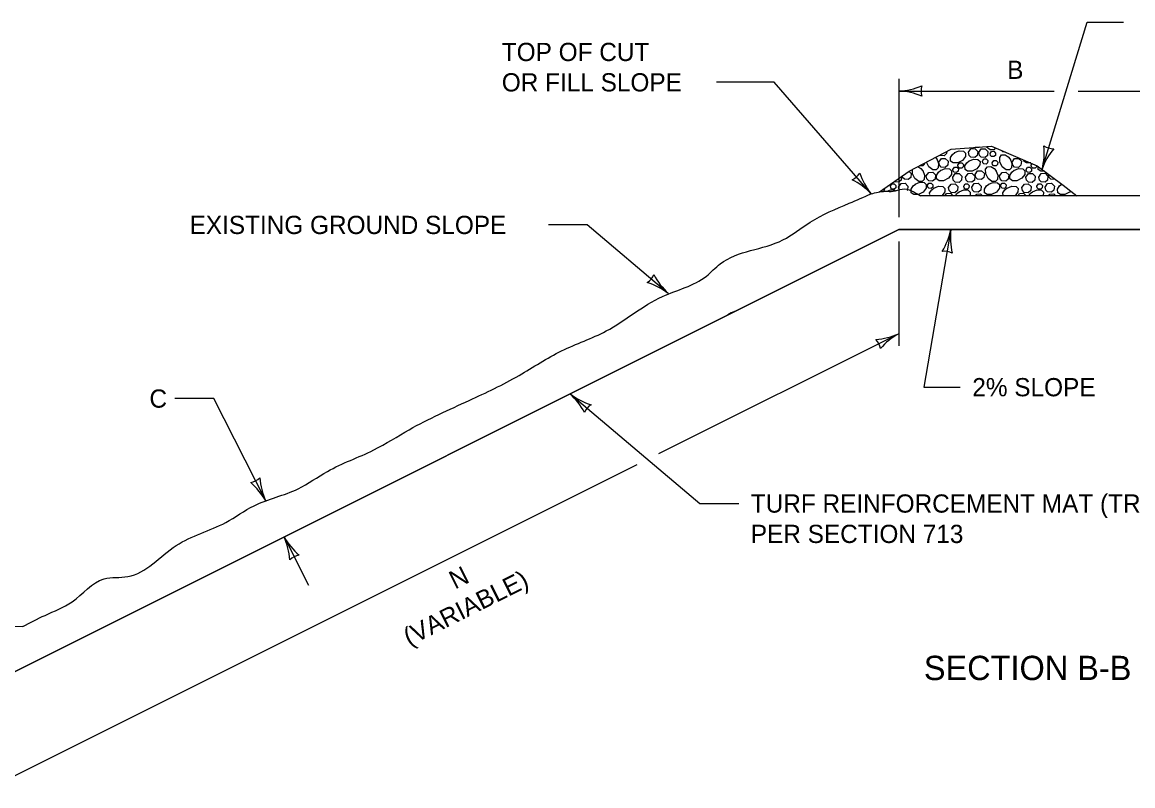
# Model space of a CAD drawing. Extents: x 49991.4 to 50021, y 49987.6 to 50011.4.
# Drawn here: x 50010.982 to 50014.64, y 49990.831 to 49993.345 of the extents above; entities that cross this region are included whole.
import ezdxf

# ---------------------------------------------------------------- set-up
doc = ezdxf.new("R2010")
doc.units = 0
for name, color, linetype in [('Level 1', 7, 'Continuous'), ('Level 2', 7, 'Continuous'), ('Level 3', 7, 'Continuous')]:
    doc.layers.add(name, color=color, linetype=linetype)

msp = doc.modelspace()

# ---------------------------------------------------------------- linework, layer by layer
at = {"layer": 'Level 1'}
for p, q in [((50014.842, 49992.7741), (50013.9411, 49992.7741)), ((50013.8692, 49992.663), (50014.7514, 49992.663))]:
    msp.add_line(p, q, dxfattribs=at)
for points in [[(50013.8062, 49992.7866), (50013.904, 49992.8548), (50014.0418, 49992.9278), (50014.1745, 49992.937), (50014.3255, 49992.8729), (50014.4104, 49992.8085), (50014.4557, 49992.7741)], [(50014.0275, 49992.9203), (50014.0268, 49992.9126), (50014.0187, 49992.9059), (50014.0058, 49992.9068), (50014.0045, 49992.9081)], [(50014.0532, 49992.916), (50014.0686, 49992.9221), (50014.0826, 49992.9208), (50014.0893, 49992.9145), (50014.0891, 49992.903), (50014.079, 49992.8901), (50014.0633, 49992.8822), (50014.0485, 49992.8819), (50014.0401, 49992.8879), (50014.0393, 49992.8997), (50014.0461, 49992.9102), (50014.0538, 49992.9164)], [(50014.0989, 49992.917), (50014.1071, 49992.9287), (50014.1202, 49992.9295), (50014.1293, 49992.92), (50014.128, 49992.9068), (50014.1199, 49992.9001), (50014.107, 49992.901), (50014.1009, 49992.9069), (50014.099, 49992.917)], [(50014.1349, 49992.9343), (50014.1332, 49992.9325), (50014.1218, 49992.9327), (50014.121, 49992.9333)], [(50014.1327, 49992.9165), (50014.1409, 49992.9282), (50014.1539, 49992.929), (50014.163, 49992.9195), (50014.1617, 49992.9063), (50014.1536, 49992.8996), (50014.1407, 49992.9005), (50014.1346, 49992.9064), (50014.1327, 49992.9165)], [(50014.1878, 49992.9314), (50014.1818, 49992.9251), (50014.1704, 49992.9253), (50014.1574, 49992.9355), (50014.1572, 49992.9358)], [(50014.17, 49992.913), (50014.1749, 49992.9199), (50014.1827, 49992.9204), (50014.1882, 49992.9147), (50014.1874, 49992.9068), (50014.1825, 49992.9028), (50014.1748, 49992.9033), (50014.1711, 49992.9069), (50014.17, 49992.9129)], [(50014.2198, 49992.9178), (50014.2124, 49992.9184), (50014.2076, 49992.923)], [(50015.5568, 49992.9155), (50015.0142, 49992.7795), (50014.842, 49992.7186), (50014.7514, 49992.663), (50013.8692, 49992.663), (50010.8919, 49991.1744), (50010.2132, 49991.2052)], [(50013.9535, 49992.8811), (50013.9531, 49992.8764), (50013.9482, 49992.8724), (50013.9405, 49992.873), (50013.9397, 49992.8737)], [(50013.9944, 49992.8953), (50014.0005, 49992.8799), (50013.9993, 49992.8658), (50013.9929, 49992.8591), (50013.9815, 49992.8594), (50013.9685, 49992.8695), (50013.9608, 49992.8849)], [(50013.9901, 49992.9005), (50013.9948, 49992.8946)], [(50014.0014, 49992.8845), (50014.0096, 49992.8961), (50014.0226, 49992.8969), (50014.0317, 49992.8874), (50014.0304, 49992.8742), (50014.0223, 49992.8675), (50014.0094, 49992.8684), (50014.0033, 49992.8743), (50014.0014, 49992.8845)], [(50014.0643, 49992.8749), (50014.0692, 49992.8819), (50014.077, 49992.8823), (50014.0825, 49992.8767), (50014.0817, 49992.8688), (50014.0768, 49992.8647), (50014.0691, 49992.8653), (50014.0654, 49992.8688), (50014.0643, 49992.8749)], [(50014.1008, 49992.8886), (50014.1161, 49992.8947), (50014.1302, 49992.8935), (50014.1369, 49992.8871), (50014.1367, 49992.8757), (50014.1265, 49992.8627), (50014.1108, 49992.8548), (50014.096, 49992.8546), (50014.0877, 49992.8605), (50014.0869, 49992.8723), (50014.0937, 49992.8828), (50014.1014, 49992.889)], [(50014.1446, 49992.8883), (50014.1495, 49992.8953), (50014.1574, 49992.8958), (50014.1628, 49992.8901), (50014.162, 49992.8822), (50014.1572, 49992.8782), (50014.1494, 49992.8787), (50014.1458, 49992.8823), (50014.1446, 49992.8883)], [(50014.1769, 49992.8826), (50014.1818, 49992.8896), (50014.1896, 49992.89), (50014.1951, 49992.8844), (50014.1943, 49992.8764), (50014.1895, 49992.8724), (50014.1817, 49992.873), (50014.1781, 49992.8765), (50014.1769, 49992.8826)], [(50014.2356, 49992.8953), (50014.2417, 49992.8799), (50014.2405, 49992.8658), (50014.2341, 49992.8591), (50014.2227, 49992.8594), (50014.2097, 49992.8695), (50014.2019, 49992.8852), (50014.2016, 49992.9), (50014.2075, 49992.9083), (50014.2193, 49992.9091), (50014.2299, 49992.9024), (50014.236, 49992.8946)], [(50014.2426, 49992.8845), (50014.2508, 49992.8961), (50014.2639, 49992.8969), (50014.273, 49992.8874), (50014.2717, 49992.8742), (50014.2636, 49992.8675), (50014.2507, 49992.8684), (50014.2446, 49992.8743), (50014.2426, 49992.8845)], [(50014.3037, 49992.8822), (50014.2897, 49992.8819), (50014.2814, 49992.8879), (50014.2811, 49992.8918)], [(50013.9031, 49992.8542), (50013.91, 49992.8471), (50013.9087, 49992.8338), (50013.9006, 49992.8271), (50013.8877, 49992.8281), (50013.8816, 49992.834), (50013.8807, 49992.8386)], [(50013.948, 49992.8566), (50013.9541, 49992.8412), (50013.9529, 49992.8272), (50013.9465, 49992.8205), (50013.9351, 49992.8207), (50013.9221, 49992.8308), (50013.9142, 49992.8465), (50013.914, 49992.8601)], [(50013.9325, 49992.8699), (50013.9422, 49992.8637), (50013.9484, 49992.856)], [(50013.9598, 49992.8394), (50013.968, 49992.851), (50013.9811, 49992.8518), (50013.9902, 49992.8424), (50013.9889, 49992.8291), (50013.9808, 49992.8224), (50013.9679, 49992.8233), (50013.9618, 49992.8292), (50013.9598, 49992.8394)], [(50014.0071, 49992.8574), (50014.0224, 49992.8634), (50014.0365, 49992.8622), (50014.0432, 49992.8559), (50014.043, 49992.8444), (50014.0328, 49992.8314), (50014.0171, 49992.8236), (50014.0023, 49992.8233), (50013.994, 49992.8292), (50013.9932, 49992.841), (50014, 49992.8516), (50014.0077, 49992.8577)], [(50014.0468, 49992.8351), (50014.055, 49992.8467), (50014.0681, 49992.8475), (50014.0772, 49992.838), (50014.0759, 49992.8248), (50014.0678, 49992.8181), (50014.0549, 49992.819), (50014.0488, 49992.8249), (50014.0468, 49992.8351)], [(50014.0473, 49992.8607), (50014.0523, 49992.8677), (50014.0601, 49992.8681), (50014.0656, 49992.8625), (50014.0648, 49992.8545), (50014.0599, 49992.8505), (50014.0522, 49992.8511), (50014.0485, 49992.8546), (50014.0474, 49992.8607)], [(50014.0891, 49992.8355), (50014.0973, 49992.8472), (50014.1104, 49992.8479), (50014.1195, 49992.8385), (50014.1182, 49992.8253), (50014.1101, 49992.8186), (50014.0971, 49992.8195), (50014.0911, 49992.8254), (50014.0891, 49992.8355)], [(50014.1209, 49992.8441), (50014.1291, 49992.8557), (50014.1422, 49992.8565), (50014.1513, 49992.8471), (50014.1499, 49992.8338), (50014.1419, 49992.8271), (50014.1289, 49992.8281), (50014.1229, 49992.834), (50014.1209, 49992.8441)], [(50014.1893, 49992.8566), (50014.1953, 49992.8412), (50014.1941, 49992.8272), (50014.1878, 49992.8205), (50014.1763, 49992.8207), (50014.1633, 49992.8308), (50014.1555, 49992.8465), (50014.1552, 49992.8613), (50014.1611, 49992.8697), (50014.1729, 49992.8705), (50014.1835, 49992.8637), (50014.1897, 49992.856)], [(50014.2011, 49992.8394), (50014.2093, 49992.851), (50014.2224, 49992.8518), (50014.2314, 49992.8424), (50014.2301, 49992.8291), (50014.222, 49992.8224), (50014.2091, 49992.8233), (50014.203, 49992.8292), (50014.2011, 49992.8394)], [(50014.2483, 49992.8574), (50014.2637, 49992.8634), (50014.2778, 49992.8622), (50014.2844, 49992.8559), (50014.2842, 49992.8444), (50014.2741, 49992.8314), (50014.2584, 49992.8236), (50014.2436, 49992.8233), (50014.2352, 49992.8292), (50014.2345, 49992.841), (50014.2412, 49992.8516), (50014.249, 49992.8577)], [(50014.288, 49992.8351), (50014.2962, 49992.8467), (50014.3093, 49992.8475), (50014.3184, 49992.838), (50014.3171, 49992.8248), (50014.309, 49992.8181), (50014.2961, 49992.819), (50014.29, 49992.8249), (50014.2881, 49992.8351)], [(50014.2886, 49992.8607), (50014.2935, 49992.8677), (50014.3014, 49992.8681), (50014.3068, 49992.8625), (50014.306, 49992.8545), (50014.3012, 49992.8505), (50014.2934, 49992.8511), (50014.2898, 49992.8546), (50014.2886, 49992.8607)], [(50014.3055, 49992.8749), (50014.309, 49992.8799)], [(50014.3234, 49992.8738), (50014.3229, 49992.8688), (50014.3181, 49992.8647), (50014.3103, 49992.8653), (50014.3067, 49992.8688), (50014.3055, 49992.8749)], [(50014.3494, 49992.8548), (50014.3373, 49992.8546), (50014.3289, 49992.8605), (50014.3283, 49992.8709)], [(50014.3303, 49992.8355), (50014.3385, 49992.8472), (50014.3516, 49992.8479), (50014.3607, 49992.8385), (50014.3594, 49992.8253), (50014.3513, 49992.8186), (50014.3384, 49992.8195), (50014.3323, 49992.8254), (50014.3303, 49992.8355)], [(50014.3844, 49992.8282), (50014.3831, 49992.8271), (50014.3702, 49992.8281), (50014.3641, 49992.834), (50014.3621, 49992.8441)], [(50013.8418, 49992.8057), (50013.8468, 49992.8127), (50013.8546, 49992.8132), (50013.8601, 49992.8075), (50013.8593, 49992.7996), (50013.8544, 49992.7955), (50013.8467, 49992.7961), (50013.843, 49992.7996), (50013.8419, 49992.8057)], [(50013.878, 49992.8367), (50013.8769, 49992.8253), (50013.8688, 49992.8186), (50013.8559, 49992.8195), (50013.8549, 49992.8205)], [(50013.8687, 49992.8027), (50013.8769, 49992.8143), (50013.89, 49992.8151), (50013.8991, 49992.8057), (50013.8978, 49992.7924), (50013.8969, 49992.7917)], [(50013.9237, 49992.8122), (50013.9391, 49992.8183), (50013.9532, 49992.8171), (50013.9598, 49992.8107), (50013.9596, 49992.7993), (50013.9495, 49992.7863), (50013.9338, 49992.7784), (50013.919, 49992.7782), (50013.9106, 49992.7841), (50013.9099, 49992.7959), (50013.9166, 49992.8064), (50013.9244, 49992.8126)], [(50013.9636, 49992.8084), (50013.9685, 49992.8154), (50013.9763, 49992.8158), (50013.9818, 49992.8102), (50013.981, 49992.8023), (50013.9761, 49992.7982), (50013.9684, 49992.7988), (50013.9647, 49992.8023), (50013.9636, 49992.8084)], [(50014.0334, 49992.8009), (50014.0416, 49992.8126), (50014.0546, 49992.8133), (50014.0637, 49992.8039), (50014.0624, 49992.7907), (50014.0543, 49992.7839), (50014.0414, 49992.7849), (50014.0353, 49992.7908), (50014.0334, 49992.8009)], [(50014.0831, 49992.8057), (50014.088, 49992.8127), (50014.0959, 49992.8132), (50014.1013, 49992.8075), (50014.1005, 49992.7996), (50014.0957, 49992.7955), (50014.0879, 49992.7961), (50014.0843, 49992.7996), (50014.0831, 49992.8057)], [(50014.11, 49992.8027), (50014.1181, 49992.8143), (50014.1312, 49992.8151), (50014.1403, 49992.8057), (50014.139, 49992.7924), (50014.1309, 49992.7857), (50014.118, 49992.7867), (50014.1119, 49992.7926), (50014.11, 49992.8027)], [(50014.165, 49992.812), (50014.1803, 49992.8181), (50014.1944, 49992.8169), (50014.2011, 49992.8105), (50014.2009, 49992.7991), (50014.1907, 49992.7861), (50014.175, 49992.7782), (50014.1602, 49992.778), (50014.1519, 49992.7839), (50014.1511, 49992.7957), (50014.1578, 49992.8062), (50014.1656, 49992.8124)], [(50014.2048, 49992.8084), (50014.2097, 49992.8154), (50014.2176, 49992.8158), (50014.223, 49992.8102), (50014.2222, 49992.8023), (50014.2174, 49992.7982), (50014.2096, 49992.7988), (50014.206, 49992.8023), (50014.2048, 49992.8084)], [(50014.2746, 49992.8009), (50014.2828, 49992.8126), (50014.2959, 49992.8133), (50014.305, 49992.8039), (50014.3037, 49992.7907), (50014.2956, 49992.7839), (50014.2827, 49992.7849), (50014.2766, 49992.7908), (50014.2746, 49992.8009)], [(50014.3243, 49992.8057), (50014.3293, 49992.8127), (50014.3371, 49992.8132), (50014.3426, 49992.8075), (50014.3418, 49992.7996), (50014.3369, 49992.7955), (50014.3292, 49992.7961), (50014.3255, 49992.7996), (50014.3243, 49992.8057)], [(50014.3512, 49992.8027), (50014.3594, 49992.8143), (50014.3725, 49992.8151), (50014.3816, 49992.8057), (50014.3803, 49992.7924), (50014.3722, 49992.7857), (50014.3593, 49992.7867), (50014.3532, 49992.7926), (50014.3512, 49992.8027)], [(50014.4349, 49992.7899), (50014.4319, 49992.7861), (50014.4162, 49992.7782), (50014.4014, 49992.778), (50014.3931, 49992.7839), (50014.3923, 49992.7957), (50014.3991, 49992.8062), (50014.406, 49992.8118)], [(50013.8219, 49992.7975), (50013.8212, 49992.7907), (50013.818, 49992.788)], [(50013.8313, 49992.7888), (50013.8422, 49992.7931), (50013.8563, 49992.7919), (50013.8581, 49992.7902)], [(50013.8704, 49992.7938), (50013.8687, 49992.8027)], [(50013.9713, 49992.7776), (50013.9709, 49992.7831), (50013.9777, 49992.7936), (50013.9854, 49992.7998)], [(50013.9848, 49992.7994), (50014.0001, 49992.8055), (50014.0142, 49992.8043), (50014.0209, 49992.7979), (50014.0207, 49992.7865), (50014.011, 49992.7741)], [(50014.0208, 49992.7741), (50014.0261, 49992.7817), (50014.0392, 49992.7825), (50014.0473, 49992.7741)], [(50014.0564, 49992.7741), (50014.061, 49992.7812), (50014.0687, 49992.7874)], [(50014.0681, 49992.787), (50014.0834, 49992.7931), (50014.0975, 49992.7919), (50014.1042, 49992.7855), (50014.104, 49992.7741)], [(50014.1221, 49992.7741), (50014.1259, 49992.7794), (50014.1389, 49992.7802), (50014.1448, 49992.7741)], [(50014.2128, 49992.7741), (50014.2122, 49992.7831), (50014.2189, 49992.7936), (50014.2267, 49992.7998)], [(50014.226, 49992.7994), (50014.2414, 49992.8055), (50014.2555, 49992.8043), (50014.2622, 49992.7979), (50014.2619, 49992.7865), (50014.2522, 49992.7741)], [(50014.262, 49992.7741), (50014.2674, 49992.7817), (50014.2805, 49992.7825), (50014.2885, 49992.7741)], [(50014.2976, 49992.7741), (50014.3022, 49992.7812), (50014.31, 49992.7874)], [(50014.3093, 49992.787), (50014.3247, 49992.7931), (50014.3388, 49992.7919), (50014.3455, 49992.7855), (50014.3452, 49992.7741)], [(50014.3633, 49992.7741), (50014.3671, 49992.7794), (50014.3802, 49992.7802), (50014.3861, 49992.7741)], [(50010.8919, 49991.1744), (50013.8692, 49992.663)], [(50013.3286, 49992.3927), (50013.3173, 49992.3888), (50013.3059, 49992.3819), (50013.3058, 49992.3813)], [(50010.9846, 49991.3557), (50010.92, 49991.353), (50010.6892, 49991.3333), (50010.503, 49991.3318)]]:
    msp.add_lwpolyline(points, dxfattribs=at)
for points in [[(50010.9846, 49991.3557), (50011.0576, 49991.3922), (50011.1465, 49991.4367), (50011.2518, 49991.5121), (50011.3299, 49991.52), (50011.4894, 49991.6222), (50011.6526, 49991.6979), (50011.7466, 49991.7534), (50011.8911, 49991.8089), (50011.9879, 49991.8664), (50012.14, 49991.9368), (50012.2573, 49992.0036), (50012.4546, 49992.1001), (50012.6187, 49992.1823), (50012.7588, 49992.2633), (50012.9057, 49992.3286), (50013.0913, 49992.4424), (50013.2357, 49992.5091), (50013.2811, 49992.5497), (50013.4874, 49992.6283), (50013.5772, 49992.6869), (50013.7063, 49992.7492), (50013.7782, 49992.7804)], [(50013.7782, 49992.7804), (50013.825, 49992.7886), (50013.8509, 49992.789), (50013.8801, 49992.7959), (50013.9411, 49992.7741)]]:
    msp.add_spline(points, degree=3, dxfattribs=at)
at = {"layer": 'Level 3'}
for p, q in [((50014.3412, 49992.861), (50014.4902, 49993.3454)), ((50014.4901, 49993.3454), (50014.6097, 49993.3454)), ((50013.4591, 49993.1475), (50013.2687, 49993.1475)), ((50013.7782, 49992.7804), (50013.4591, 49993.1475)), ((50013.8692, 49993.1588), (50013.8692, 49992.703)), ((50013.8692, 49993.1188), (50014.3805, 49993.1188)), ((50014.4605, 49993.1188), (50014.842, 49993.1188)), ((50012.843, 49992.6779), (50012.7154, 49992.6779)), ((50013.1099, 49992.4522), (50012.843, 49992.6779)), ((50014.041, 49992.663), (50013.9519, 49992.1436)), ((50013.8692, 49992.623), (50013.8692, 49992.2796)), ((50013.8692, 49992.3196), (50013.078, 49991.924)), ((50012.7869, 49992.1219), (50013.2144, 49991.7605)), ((50013.9519, 49992.1436), (50014.0715, 49992.1436)), ((50011.6132, 49992.1061), (50011.4856, 49992.1061)), ((50011.7843, 49991.7695), (50011.6132, 49992.1061)), ((50013.0064, 49991.8882), (50010.8919, 49990.831)), ((50013.2144, 49991.7605), (50013.342, 49991.7605)), ((50011.8446, 49991.6507), (50011.9253, 49991.492))]:
    msp.add_line(p, q, dxfattribs=at)
for centre, radius, start, end in [((50013.8577, 49993.3515), 0.233, 272.8273, 292.0772), ((50013.86, 49992.8967), 0.2223, 67.456, 87.6395), ((50013.9974, 49993.1188), 0.0548, 162.1388, 197.8612), ((50014.1154, 49992.9184), 0.233, 345.7341, 4.9839), ((50014.5508, 49992.787), 0.2223, 140.3628, 160.5463), ((50014.3789, 49992.9836), 0.0548, 235.0456, 270.7679), ((50013.6941, 49992.8772), 0.0548, 293.1389, 328.8612), ((50013.9519, 49992.9192), 0.2223, 198.4561, 218.6396), ((50013.6101, 49992.6191), 0.233, 43.8274, 63.0772), ((50013.8132, 49992.7118), 0.233, 328.6692, 347.919), ((50014.2618, 49992.6363), 0.2223, 173.1068, 193.2903), ((50014.0204, 49992.5364), 0.0548, 62.8851, 98.6075), ((50013.012, 49992.535), 0.0548, 301.9353, 337.6577), ((50012.9685, 49992.2671), 0.233, 52.6238, 71.8736), ((50013.2603, 49992.616), 0.2223, 207.2525, 227.436), ((50013.778, 49992.5224), 0.2223, 274.0203, 294.2038), ((50013.7545, 49992.2623), 0.0548, 8.7031, 44.4255), ((50013.9835, 49992.1166), 0.233, 119.3916, 138.6414), ((50012.6365, 49991.9581), 0.2223, 27.2525, 47.436), ((50012.9283, 49992.307), 0.233, 232.6238, 251.8736), ((50012.8848, 49992.0391), 0.0548, 121.9353, 157.6577), ((50011.7262, 49991.8838), 0.0548, 279.0771, 314.7994), ((50011.582, 49991.6538), 0.233, 29.7656, 49.0154), ((50011.9865, 49991.862), 0.2223, 184.3943, 204.5778), ((50011.6424, 49991.5583), 0.2223, 4.3943, 24.5778), ((50012.0469, 49991.7664), 0.233, 209.7656, 229.0154), ((50011.9027, 49991.5364), 0.0548, 99.0771, 134.7994)]:
    msp.add_arc(centre, radius, start, end, dxfattribs=at)

# ---------------------------------------------------------------- texts
at = {"layer": 'Level 2'}
for s, height, p in [('TOP OF CUT', 0.06, (50012.5619, 49993.2175)), ('B', 0.06, (50014.2263, 49993.1588)), ('OR FILL SLOPE', 0.06, (50012.5619, 49993.1175)), ('EXISTING GROUND SLOPE', 0.06, (50011.5336, 49992.6479)), ('2% SLOPE', 0.06, (50014.1115, 49992.1136)), ('C', 0.06, (50011.4014, 49992.0761)), ('TURF REINFORCEMENT MAT (TRM)', 0.06, (50013.382, 49991.7305)), ('PER SECTION 713', 0.06, (50013.382, 49991.6305)), ('SECTION B-B', 0.08, (50013.9519, 49991.1791))]:
    msp.add_text(s, height=height, dxfattribs=at).set_placement(p)
for s, p in [('(VARIABLE)', (50012.257, 49991.2899)), ('N', (50012.4078, 49991.4771))]:
    msp.add_text(s, height=0.06, rotation=26.5643, dxfattribs=at).set_placement(p)

doc.saveas('drawing.dxf')
